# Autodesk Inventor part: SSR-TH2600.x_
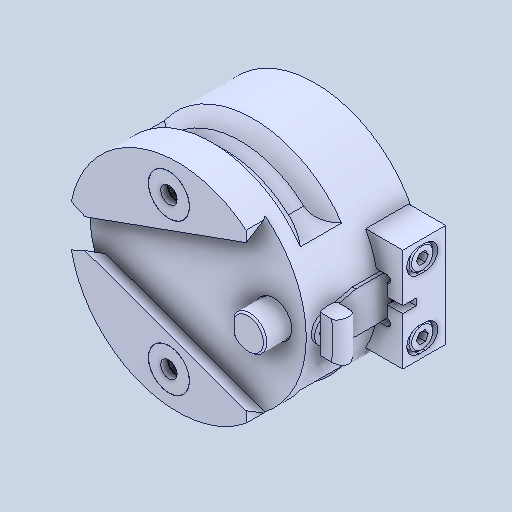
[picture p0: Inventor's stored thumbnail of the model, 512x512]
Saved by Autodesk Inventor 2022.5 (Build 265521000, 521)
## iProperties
Created: 2024-03
Part Number: SSR-TH2600.x_
Material: 一般
Document SubType Name: Modeling
Designer: ImaoCorp
Density: 1 g/cm^3
Appearance: 既定
Author: ImaoCorp
Sending System: SOLIDWORKS 2022-2022290
MC: AMD64
MC_MODEL: Intel64 Family 6 Model 60 Stepping 3, GenuineIntel
OS: Windows_NT
FRU: Parasolid Version 33.1, build 260,  4-25-2022
FORMAT: text
GUISE: transmit
KEY: FILESSR-TH2600.x_t
DATE: Wed Mar  6 09:23:54 2024
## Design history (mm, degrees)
feature "Base1"
node "ソリッド1"
